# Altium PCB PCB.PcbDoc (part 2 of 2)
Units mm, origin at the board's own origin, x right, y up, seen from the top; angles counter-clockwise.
Board outline 106 x 80 mm, 4 copper layers (TOP, GND, SIG, BOTTOM), stack 1.586 mm thick; 94 components, 82 nets, 532 pads, 292 vias.
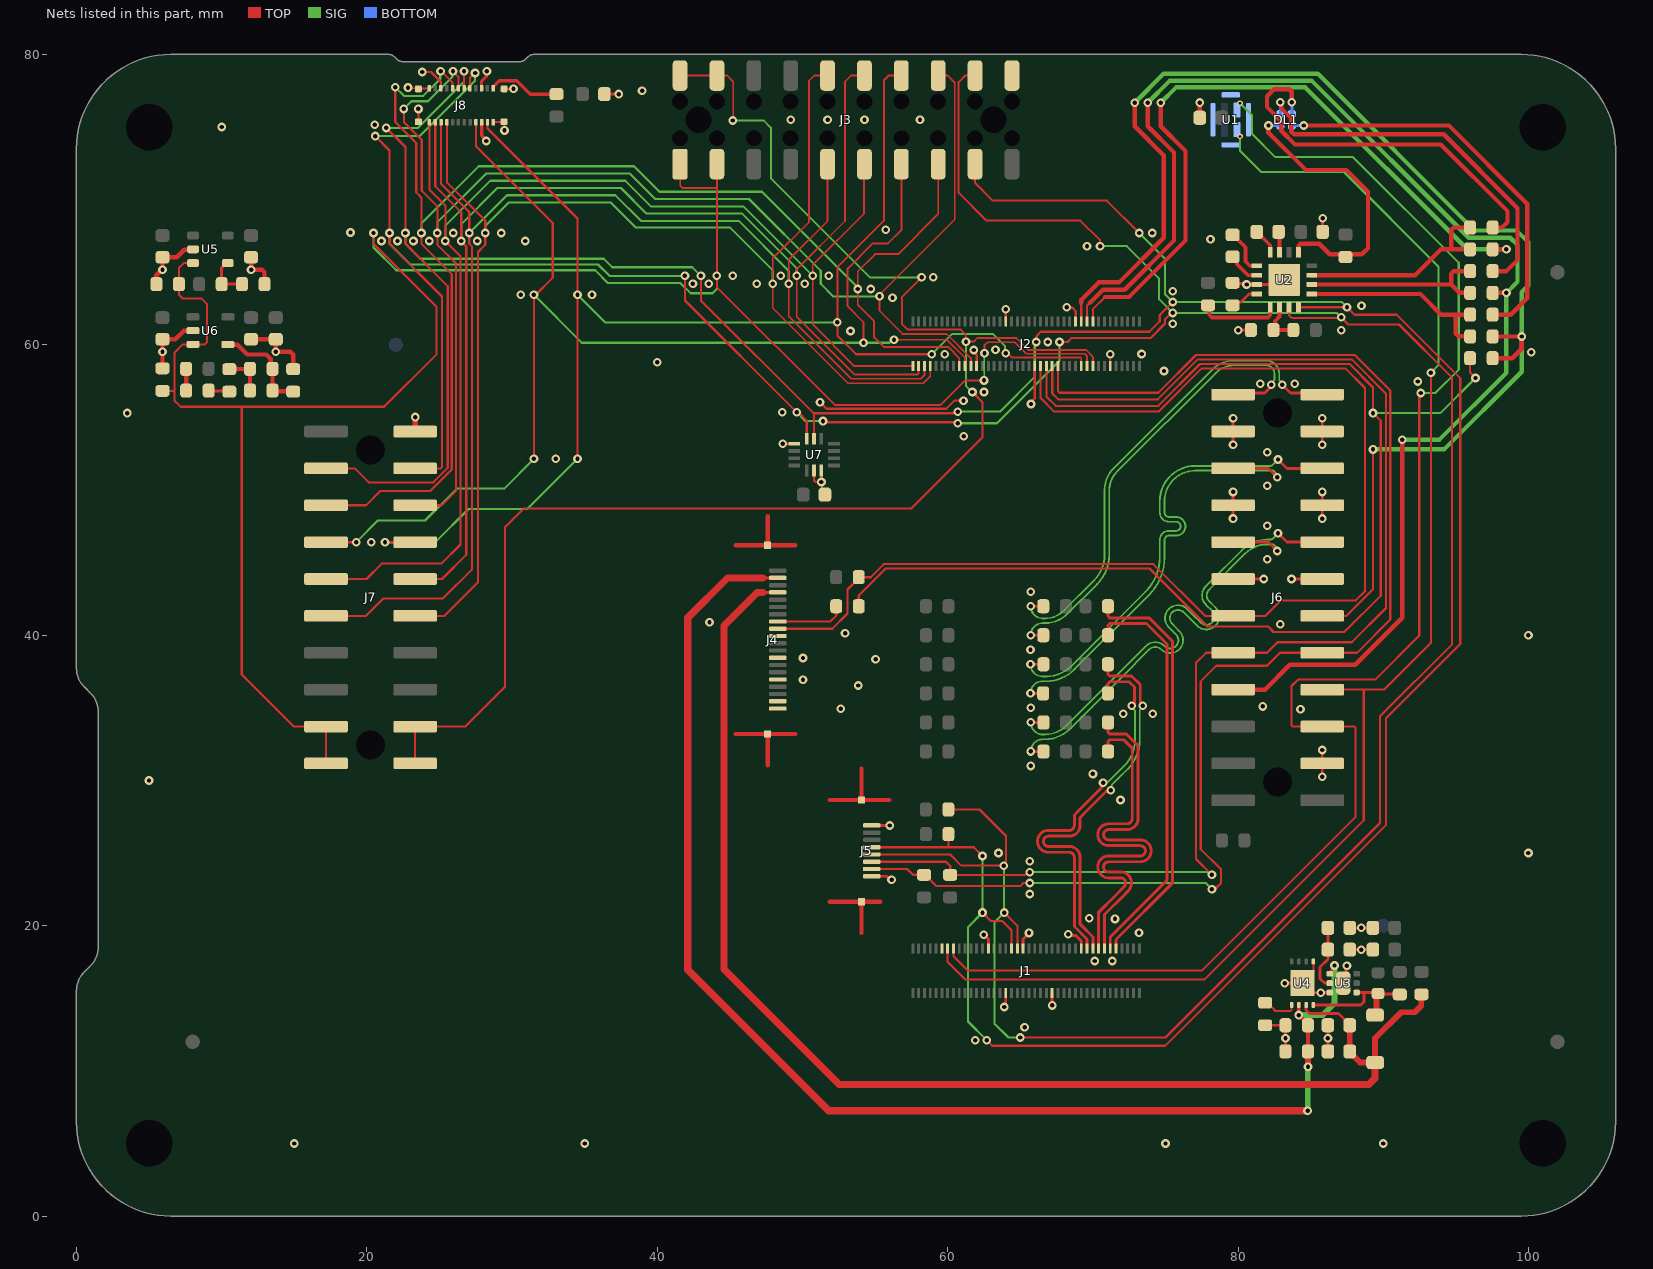
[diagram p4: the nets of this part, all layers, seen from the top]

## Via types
v1: diameter 0.6, hole 0.3, TOP to BOTTOM, tented both sides, 288 vias
v2: diameter 0.4, hole 0.2, TOP to BOTTOM, tented both sides, 4 vias

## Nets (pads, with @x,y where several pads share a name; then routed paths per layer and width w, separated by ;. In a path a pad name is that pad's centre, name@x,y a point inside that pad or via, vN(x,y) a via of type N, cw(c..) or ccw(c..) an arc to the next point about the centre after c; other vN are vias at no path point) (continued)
DOUT4: J2.8 J3.10 J7.12 J8.21 | length 94.1
  TOP w0.127: J3.10@51.731,78.55 50.819,78.55 50.45,78.182 50.45,68.45 47.956,65.956 v1(47.956,64.201) 47.956,62.538 53.136,57.358 58.335,57.358 58.801,57.824 J2.8@58.801,58.535
  TOP w0.15: J7.12@23.326,41.331 25.331,41.331 27.648,43.648 27.648,66.393 28.156,66.901 v1(28.156,67.701) 28.156,68.56 25.509,71.207 J8.21@25.509,75.334
  SIG w0.15: v1(28.156,67.701) 28.156,68.186 29.771,69.8 36.8,69.8 38.508,68.092 44.992,68.092 47.956,65.128 v1(47.956,64.201)
DOUT5: J2.6 J3.9 J7.11 J8.22 | length 92.6
  TOP w0.127: J3.9@51.731,72.45 51.731,68.531 49.056,65.856 v1(49.056,64.201) 49.056,61.973 53.366,57.663 58.163,57.663 58.401,57.901 J2.6@58.401,58.535
  TOP w0.15: J7.11@17.186,41.331 19.931,41.331 21.131,42.531 25.231,42.531 27.248,44.548 27.248,66.766 27.056,66.958 v1(27.056,67.701) 27.056,69.151 25.109,71.098 J8.22@25.109,75.334
  SIG w0.15: v1(27.056,67.701) 29.656,70.3 37.116,70.3 38.877,68.54 45.603,68.54 49.056,65.086 v1(49.056,64.201)
DOUT6: J2.4 J3.12 J7.10 J8.23 | length 92.7
  TOP w0.127: J3.12@54.271,78.55 53.35,78.55 52.931,78.131 52.931,68.531 49.606,65.206 49.606,61.938 53.58,57.963 57.927,57.963 58.001,58.038 J2.4@58.001,58.535
  TOP w0.15: J7.10@23.326,43.871 25.171,43.871 26.848,45.548 26.848,66.774 26.506,67.117 26.506,69.131 24.709,70.928 J8.23@24.709,75.334
  SIG w0.15: v1(26.506,67.151) 26.506,68.317 28.989,70.8 37.5,70.8 39.26,69.04 45.848,69.04 49.606,65.281 v1(49.606,64.751)
DOUT7: J2.2 J3.11 J7.9 J8.24 | length 91.2
  TOP w0.127: J3.11@54.271,72.45 54.24,72.419 54.24,69.04 50.706,65.506 v1(50.706,64.751) 50.706,61.407 53.578,58.535 J2.2@57.601,58.535
  TOP w0.15: J7.9@17.186,43.871 19.971,43.871 21.031,44.931 25.131,44.931 26.448,46.248 26.448,66.109 v1(25.406,67.151) 25.406,69.594 24.309,70.691 J8.24@24.309,75.334
  SIG w0.15: v1(25.406,67.151) 25.406,68.2 28.506,71.3 37.8,71.3 39.56,69.54 45.917,69.54 v1(50.706,64.751)
DSI_CK_2_N: J6.5 R32.1 | length 33.2
  TOP w0.2: v1(65.707,36) R32.1@66.58,36 ; J6.5@79.659,51.494 82.093,51.494 v1(82.707,50.88)
  SIG w0.127: v1(65.707,36) cw(c66.543,36) 66.543,36.837 ccw(c66.759,39.619) 68.731,37.645 73.872,42.785 ; 73.872,42.786 ccw(c71.307,45.35) 74.934,45.35 74.934,45.715 74.934,46.55 cw(c75.247,46.55) 75.247,46.863 75.736,46.863 ccw(c75.736,47.504) 75.736,48.144 75.247,48.144 cw(c75.247,48.458) 74.934,48.458 74.934,48.685 74.934,49.219 cw(c77.054,49.219) 77.054,51.339 82.385,51.339 cw(c82.385,51.212) 82.474,51.303 82.58,51.197 cw(c82.489,51.108) 82.616,51.108 82.616,50.971 v1(82.707,50.88)
DSI_CK_2_P: J6.6 R31.1 | length 33.2
  TOP w0.2: v1(65.707,38) R31.1@66.58,38 ; v1(82.751,52.108) 83.365,51.494 J6.6@85.799,51.494
  SIG w0.127: v1(65.707,38) ccw(c66.543,38) 66.54,37.164 ccw(c66.543,38) 66.543,37.164 cw(c66.543,36.836) 66.57,37.162 ccw(c66.759,39.619) 68.502,37.878 73.639,43.015 ccw(c71.302,45.352) 73.64,43.016 ccw(c71.302,45.352) 74.607,45.352 74.607,45.715 74.607,46.55 cw(c75.247,46.55) 75.247,47.19 75.736,47.19 ccw(c75.736,47.504) 75.736,47.817 75.247,47.817 cw(c75.247,48.458) 74.607,48.458 74.607,48.685 74.607,49.219 cw(c77.054,49.219) 77.054,51.666 82.257,51.666 ccw(c82.257,51.793) 82.347,51.703 ; 82.347,51.703 v1(82.751,52.108)
DSI_CK_3_N: J1.20 R4.1 | length 27.2
  TOP w0.2: J1.20@69.601,18.435 69.601,19.06 68.727,19.934 68.727,24.4 68.727,24.7 ccw(c68.373,24.7) 68.373,25.054 66.941,25.054 cw(c66.941,25.808) 66.941,26.562 68.373,26.562 ccw(c68.373,26.916) 68.727,26.916 68.727,27.624 69.029,27.926 70.63,29.527 70.63,29.774 v1(70.706,29.851) ; R4.1@71.039,36 71.039,36.683 71.156,36.8 72.5,36.8 72.864,36.437 72.864,35.326 v1(72.689,35.151)
  SIG w0.127: v1(70.706,29.851) 70.777,29.921 71.076,29.921 71.622,30.467 72.156,31.001 ccw(c70.36,32.797) 72.9,32.797 72.9,34.84 72.689,35.051 v1(72.689,35.151)
DSI_CK_3_P: J1.18 R3.1 | length 27.7
  TOP w0.2: J1.18@70.001,18.435 70.001,19.226 69.127,20.1 69.127,24.4 69.127,24.7 ccw(c68.373,24.7) 68.373,25.454 66.941,25.454 cw(c66.941,25.808) 66.941,26.162 68.373,26.162 ccw(c68.373,26.916) 69.127,26.916 69.127,27.458 69.595,27.926 70.913,29.244 71.16,29.244 v1(71.237,29.32) ; R3.1@71.039,38 71.039,37.317 71.156,37.2 72.089,37.2 72.666,37.2 73.264,36.602 73.264,35.326 v1(73.438,35.151)
  SIG w0.127: v1(71.237,29.32) 71.307,29.391 71.307,29.69 71.757,30.14 72.389,30.772 ccw(c70.365,32.795) 73.227,32.795 73.227,32.933 73.227,34.84 73.438,35.051 v1(73.438,35.151)
DSI_D0_2_N: J6.9 R34.1 | length 33.2
  TOP w0.2: v1(65.727,32) R34.1@66.6,32 ; J6.9@79.659,46.414 82.093,46.414 v1(82.707,45.8)
  SIG w0.127: v1(65.727,32) cw(c66.564,32) 66.564,32.837 66.71,32.837 ccw(c66.71,35.242) 68.41,33.541 71.942,37.073 73.9,39.031 cw(c74.299,38.633) 74.697,39.031 ccw(c75.327,39.661) 75.905,38.983 75.909,38.983 76.005,39.079 76.005,39.083 ccw(c75.327,39.661) 75.957,40.29 75.693,40.553 75.466,40.781 cw(c75.865,41.179) 75.466,41.578 cw(c75.865,41.179) 76.263,41.578 ; 76.264,41.577 77.187,40.654 ccw(c77.817,41.283) 78.447,40.654 ccw(c77.817,41.283) 78.447,41.913 78.415,41.945 78.013,42.347 cw(c78.411,42.745) 78.013,43.143 78.173,43.304 80.507,45.638 cw(c82.007,44.138) 82.007,46.259 82.385,46.259 cw(c82.385,46.132) 82.474,46.223 82.58,46.117 cw(c82.489,46.028) 82.616,46.028 82.616,45.891 v1(82.707,45.8)
DSI_D0_2_P: J6.10 R33.1 | length 33.2
  TOP w0.2: v1(65.727,34) R33.1@66.6,34 ; v1(82.751,47.028) 83.365,46.414 J6.10@85.799,46.414
  SIG w0.127: v1(65.727,34) ccw(c66.564,34) 66.564,33.163 66.707,33.163 ccw(c66.707,35.248) 68.181,33.774 71.711,37.304 73.669,39.262 cw(c74.299,38.633) 74.929,39.262 ; 74.929,39.262 ccw(c75.327,39.661) 75.725,39.262 ccw(c75.327,39.661) 75.725,40.059 75.235,40.549 cw(c75.865,41.179) 75.234,41.808 75.235,41.809 cw(c75.865,41.179) 76.442,41.857 76.446,41.857 76.923,41.381 77.419,40.885 ccw(c77.817,41.283) 78.215,40.885 ccw(c77.817,41.283) 78.215,41.682 77.782,42.115 cw(c78.411,42.745) 77.782,43.375 77.942,43.535 80.279,45.872 cw(c82.003,44.148) 82.003,46.586 82.257,46.586 ccw(c82.257,46.713) 82.347,46.623 ; 82.347,46.623 v1(82.751,47.028)
DSI_D0_3_N: J1.16 R6.1 | length 26.2
  TOP w0.2: J1.16@70.401,18.435 70.401,20.928 71.557,22.084 72.16,22.688 ccw(c71.91,22.938) 71.91,23.292 71.091,23.292 cw(c71.091,24.046) 70.337,24.046 cw(c71.091,24.046) 71.091,24.8 73.266,24.8 ccw(c73.266,25.154) 73.62,25.154 ccw(c73.266,25.154) 73.266,25.508 71.091,25.508 cw(c71.091,26.262) 70.337,26.262 cw(c71.091,26.262) 71.091,27.016 72.363,27.016 ccw(c72.363,27.37) 72.717,27.37 72.717,29.16 72.717,32.217 72.134,32.8 71.167,32.8 71.05,32.683 R6.1@71.05,32
DSI_D0_3_P: J1.14 R5.1 | length 26.8
  TOP w0.2: J1.14@70.801,18.435 70.801,20.763 72.122,22.084 72.443,22.405 ccw(c71.91,22.938) 71.91,23.692 71.091,23.692 cw(c71.091,24.046) 70.737,24.046 cw(c71.091,24.046) 71.091,24.4 73.266,24.4 ccw(c73.266,25.154) 74.02,25.154 ccw(c73.266,25.154) 73.266,25.908 71.091,25.908 cw(c71.091,26.262) 70.737,26.262 cw(c71.091,26.262) 71.091,26.616 72.363,26.616 ccw(c72.363,27.37) 73.117,27.37 73.117,29.16 73.117,32.383 72.3,33.2 71.167,33.2 71.05,33.317 R5.1@71.05,34
DSI_D1_2_N: J6.1 R36.1 | length 33
  TOP w0.2: v1(65.716,40) R36.1@66.589,40 ; J6.1@79.659,56.574 79.764,56.679 81.836,56.679 v1@82.352,57.194
  SIG w0.127: v1(65.716,40) cw(c66.553,40) 66.553,40.837 66.709,40.837 ccw(c66.709,43.003) 68.24,41.471 70.296,43.526 ccw(c68.272,45.55) 71.134,45.55 71.134,49.975 cw(c72.982,49.975) 71.674,51.281 ; 71.675,51.282 78.452,58.059 cw(c79.759,56.752) 78.453,58.06 cw(c79.759,56.752) 79.759,58.6 81.907,58.6 cw(c81.907,58) 82.507,58 82.507,57.901 82.507,57.562 82.296,57.35 v1(82.296,57.251)
DSI_D1_2_P: J6.2 R35.1 | length 33.5
  TOP w0.2: v1(65.716,42) R35.1@66.589,42 ; v1@83.09,57.206 83.617,56.679 85.694,56.679 J6.2@85.799,56.574
  SIG w0.127: v1(65.716,42) ccw(c66.553,42) 66.553,41.164 66.707,41.164 ccw(c66.707,43.007) 68.01,41.703 70.063,43.756 ccw(c68.267,45.552) 70.807,45.552 70.807,49.977 cw(c72.977,49.977) 71.442,51.511 ; 71.443,51.511 78.223,58.291 ; 78.223,58.292 cw(c79.757,56.757) 79.757,58.927 81.907,58.927 cw(c81.907,58) 82.834,58 82.834,57.765 82.834,57.562 83.046,57.35 v1(83.046,57.251)
DSI_D1_3_N: J1.12 R8.1 | length 28
  TOP w0.2: R8.1@71.039,40 71.039,40.683 71.156,40.8 73.7,40.8 75.1,39.4 75.1,23.119 71.201,19.221 J1.12@71.201,18.435
DSI_D1_3_P: J1.10 R7.1 | length 28.6
  TOP w0.2: R7.1@71.039,42 71.039,41.317 71.156,41.2 73.866,41.2 75.5,39.566 75.5,22.954 71.601,19.055 J1.10@71.601,18.435
GND: C1.1 C4.1 C5.1 C6.1 C7.1 C8.1 C9.1 C10.1 C11.1 C12.1 C13.1 C14.1 C15.1 C16.1 C17.1 J1.22 J1.31 J1.42 J1.47 J1.54 J2.24 J2.33 J2.44 J2.57 J2.70 J3.20 J4.1 J4.2 J4.5 J4.8 J4.11 J4.FIX1 J4.FIX2 J5.1 J5.8 J5.FIX1 J5.FIX2 J6.3 J6.4 J6.7 J6.8 J6.11 J6.12 J6.22 J7.2 J8.1 J8.3 J8.10 J8.13 J8.15 J8.M1 J8.M2 J8.M3 J8.M4 R10.2 R12.1 R28.1 R29.1 R30.1 R38.1 R39.1 R42.1 R47.1 U1.5 U2.11 U2.17 U3.3 U3.7 U4.1 U4.9 U5.2 U6.2 U7.1 U7.6 U7.7 | length 115.6
  TOP w0.127: v1(22.831,77.718) 22.875,77.674 23.507,77.674 J8.M4@23.551,77.63 23.571,77.65 24.281,77.65 J8.1@24.301,77.67 ; J8.M1@23.551,75.36 v1(23.551,76.251) ; J8.13@28.725,75.318 J8.13@28.709,75.334 28.722,75.347 29.438,75.347 J8.M2@29.451,75.36 29.463,75.348 29.463,74.783 v1(29.476,74.77) ; v1(71.196,59.356) 71.199,59.353 71.199,58.538 J2.70@71.201,58.535
  TOP w0.15: v1(23.821,78.789) 24.416,78.789 25.101,78.104 J8.3@25.101,77.67 ; J8.M3@29.451,77.63 v1(30.096,77.63) ; v1(48.65,53.194) U7.1@49.425,53.194 ; U7.6@50.8,51.344 50.8,50.657 50.906,50.551 v1(51.306,50.551) ; v1(51.206,56.051) 51.659,55.598 59.905,55.598 60.465,56.158 v1(61.088,56.158) ; U7.7@51.3,51.344 51.303,51.341 51.303,50.554 v1(51.306,50.551) ; C17.1@51.55,49.682 51.353,49.878 51.353,50.504 v1(51.306,50.551) ; v1(61.789,59.643) 61.789,59.515 62.001,59.302 J2.24@62.001,58.535 ; J2.33@64.001,61.615 v1(64.001,62.461) ; v1(65.744,55.927) 65.744,56.049 66.001,56.305 J2.44@66.001,58.535 ; v1(68.2,62.6) 68.248,62.552 68.595,62.552 68.825,62.322 68.825,62.096 68.807,62.078 68.807,61.621 J2.57@68.801,61.615 ; R30.1@81.865,13.14 R28.1@83.265,13.14 ; U4.9@84.44,16.04 85.19,16.79 U4.1@85.19,17.54
  TOP w0.2: J8.10@27.901,77.67 27.901,78.151 28.227,78.477 28.227,78.8 v1(28.268,78.841) ; C13.1@36.358,77.271 v1(37.348,77.271) ; J5.1@54.769,23.406 J5.1@54.771,23.404 55.785,23.404 56.03,23.159 v1(56.139,23.159) ; J5.8@54.771,26.904 56.003,26.904 v1(56.005,26.902) ; v1(62.48,19.378) 62.499,19.378 62.801,19.076 J1.54@62.801,18.435 ; v1(63.9,14.4) 63.9,14.508 64.001,14.609 J1.47@64.001,15.355 ; J1.42@65.201,18.435 65.201,19.085 65.6,19.484 v1(65.6,19.5) ; v1(67.201,14.506) J1.31@67.201,15.355 ; v1(68.307,19.4) 68.384,19.323 68.827,19.323 69.201,18.949 J1.22@69.201,18.435 ; R12.1@79.629,64.271 79.687,64.214 80.531,64.214 v1(80.589,64.156) U2.11@81.29,64.156 82.86,64.156 U2.17@83.185,64.481 ; J6.11@79.659,43.874 v1(81.781,43.874) ; v1(79.659,48.035) J6.7@79.659,48.954 v1(79.659,49.872) ; v1(79.659,53.115) J6.3@79.659,54.034 v1(79.659,54.952) ; v1(80.008,61.009) 80.016,61.017 80.794,61.017 R10.2@80.886,60.925 ; v1(83.217,16.04) U4.9@84.44,16.04 85.104,15.376 v1(85.696,15.376) 85.703,15.383 86.308,15.383 U3.3@86.315,15.39 ; R29.1@83.265,11.34 v1(83.265,12.24) R28.1@83.265,13.14 ; v1(83.678,43.874) J6.12@85.799,43.874 ; v1(85.799,30.255) J6.22@85.799,31.174 v1(85.799,32.092) ; v1(85.799,48.035) J6.8@85.799,48.954 v1(85.799,49.872) ; v1(85.799,53.115) J6.4@85.799,54.034 v1(85.799,54.952) ; v1(85.83,68.721) v1(85.83,68.721) C4.1@85.829,67.784 ; C8.1@86.19,11.34 v1(86.19,12.24) C7.1@86.19,13.14 ; U3.7@87.24,16.04 87.423,16.222 87.423,17.167 v1(87.499,17.243) ; C9.1@87.69,18.35 87.694,18.346 v1(88.495,18.346) 89.286,18.346 C6.1@89.29,18.35 ; C10.1@87.69,19.85 87.694,19.846 v1(88.495,19.846) 89.286,19.846 C5.1@89.29,19.85 ; C4.1@85.828,67.783 C4.1@85.829,67.784
  TOP w0.22: J8.15@27.909,75.334 27.909,74.415 28.231,74.093 v1(28.231,74.043)
  TOP w0.3: R38.1@5.507,64.181 5.5,64.188 5.5,64.8 5.881,65.181 v1(5.927,65.181) C11.1@5.927,66.031 ; R42.1@5.927,58.38 v1(5.927,59.531) C14.1@5.927,60.381 ; C14.1@6.061,60.381 6.8,60.381 7.382,60.963 8.008,60.963 U6.2@8.027,60.981 ; C11.1@6.226,66.031 6.914,66.031 7.43,66.547 7.992,66.547 U5.2@8.027,66.581 ; C16.1@12.027,60.381 C15.1@13.727,60.381 ; C12.1@12.026,66.031 v1(12.027,65.181) 12.776,65.181 12.952,65.005 R39.1@12.952,64.181 ; C15.1@13.727,60.381 v1(13.727,59.531) 14.727,59.531 14.927,59.331 R47.1@14.927,58.326 ; 45.404,33.2 J4.FIX2@47.601,33.2 ; 45.404,46.2 J4.FIX1@47.601,46.2 ; 47.601,31.035 J4.FIX2@47.601,33.2 ; 47.601,48.185 J4.FIX1@47.601,46.2 ; 49.501,33.2 J4.FIX2@47.601,33.2 ; 49.501,46.2 J4.FIX1@47.601,46.2 ; 51.874,21.654 J5.FIX2@54.071,21.654 ; 51.874,28.654 J5.FIX1@54.071,28.654 ; 54.071,19.489 J5.FIX2@54.071,21.654 ; 54.071,30.819 J5.FIX1@54.071,28.654 ; 55.349,21.654 J5.FIX2@54.071,21.654 ; 55.971,28.654 J5.FIX1@54.071,28.654 ; C1.1@77.358,75.644 77.36,75.646 77.36,76.684 v1(77.363,76.687)
  TOP w0.4: J7.2@23.326,54.031 v1(23.326,55.026)
  other v1: 15,5 35,5 75,5 90,5 61.9,12.1 65.3,13 70.136,17.561 71.336,17.561 73.176,19.509 71.526,20.464 69.755,20.513 65.659,22.184 65.659,24.434 63.5,25 100,25 71.906,28.651 5,30 70.006,30.451 65.727,31 72.1,34.6 74.127,34.6 84.3,34.9 52.638,34.938 65.727,35 81.7,35.1 53.838,36.538 50.038,36.938 55.038,38.338 50.038,38.438 65.707,39 100,40 52.938,40.138 82.906,40.751 43.6,40.9 65.716,43 82.007,45.242 20.296,46.413 82.007,47.542 82.007,50.3 33.006,52.151 82.007,52.6 61.1,53.7 3.5,55.3 48.606,55.351 62.506,56.751 81.537,57.324 83.916,57.324 92.385,57.481 74.9,58.2 40,58.8 59.806,59.351 73.358,59.371 100.2,59.5 63.299,59.662 66.9,60.2 53.306,60.951 87.1,61 75.5,61.45 88.5,62.7 56.206,63.251 30.606,63.451 35.506,63.451 75.5,63.7 54.706,63.851 42.456,64.201 43.556,64.201 46.856,64.201 50.156,64.201 59.006,64.651 45.206,64.751 48.506,64.751 51.806,64.751 69.6,66.8 21.006,67.151 22.106,67.151 23.206,67.151 24.306,67.151 27.606,67.151 30.906,67.151 78.105,67.275 25.956,67.701 29.256,67.701 74.1,67.7 18.871,67.737 55.735,67.931 10,75 20.545,75.15 49.2,75.5 51.731,75.5 54.271,75.5 58.1,75.5 38.956,77.505
HREF: J2.22 J3.16 J7.6 J8.6 | length 101.1
  TOP w0.127: v1(25.931,78.85) 26.301,78.481 J8.6@26.301,77.67 ; J3.16@59.351,78.55 60.007,78.55 60.49,78.068 60.49,68.635 55.306,63.451 55.306,62.344 56.901,60.749 59.942,60.749 61.601,59.09 J2.22@61.601,58.535
  TOP w0.15: v1(22.551,76.251) 22.551,75.348 23.785,74.114 23.785,70.615 24.856,69.544 v1(24.856,67.701) 24.856,66.901 26.148,65.609 26.148,49.948 25.151,48.951 J7.6@23.326,48.951
  SIG w0.15: v1(22.551,76.251) 23.076,76.776 24.206,76.776 25.885,78.454 25.885,78.804 v1(25.931,78.85) ; v1(24.856,67.701) 24.856,68.438 28.218,71.8 38.1,71.8 39.86,70.04 46.317,70.04 51.256,65.101 51.256,64.201 52.131,63.326 55.281,63.326 v1(55.306,63.351)
LEDA_4: C7.2 C8.2 D1.C J4.17 R25.2 U4.7 | length 91.9
  TOP w0.2: 47.27,42.944 47.276,42.95 J4.17@48.301,42.95 ; U4.7@84.69,14.54 84.69,14.19 84.928,13.952 86.928,13.952 C7.2@87.69,13.19
  TOP w0.4: C8.2@87.69,11.34 87.69,11.29 88.41,10.57 D1.C@89.44,10.57 89.44,12.24 91.24,14.04 92.171,14.04 92.62,14.489 92.62,15.245 R25.2@92.64,15.265 ; C8.2@87.69,11.44 C7.2@87.69,13.19
  TOP w0.5: 47.27,42.944 46.881,42.944 44.6,40.664 44.6,16.995 52.539,9.056 89.008,9.056 89.44,9.488 D1.C@89.44,10.57
LEDK_4: J4.19 R28.2 R29.2 U3.1 U4.6 | length 92
  TOP w0.2: 47.265,43.94 47.276,43.95 J4.19@48.301,43.95 ; U3.1@86.315,16.69 86.34,16.69 86.44,16.79 86.44,16.941 86.646,17.147 v1(86.646,17.255)
  TOP w0.25: U4.6@84.19,14.54 v1(84.19,13.84) 84.815,13.215 R28.2@84.815,13.14 R29.2@84.815,11.34
  TOP w0.4: v1(84.815,10.275) R29.2@84.815,11.34
  TOP w0.5: 47.265,43.94 44.84,43.94 42.1,41.2 42.1,16.955 51.805,7.25 v1(84.79,7.25)
  SIG w0.4: v1(84.19,13.84) 85.83,13.84 86.646,14.656 v1(86.646,17.255) ; v1(84.79,7.25) 84.803,7.262 84.803,10.262 v1(84.815,10.275)
nBLUE_1: J2.63 R50.2 | length 49.2
  TOP w0.15: J2.63@70.001,61.615 70.001,62.451 70.85,63.3
  TOP w0.3: 70.85,63.3 72.5,63.3 76.385,67.185 76.385,73.351 74.685,75.051 v1(74.685,76.681) ; R50.2@97.535,66.581 v1(98.485,66.581)
  SIG w0.3: v1(74.685,76.681) 75.735,77.731 84.635,77.731 95.785,66.581 v1(98.485,66.581)
NetC2_1: C2.1 U2.8 | length 1.8
  TOP w0.25: C2.1@81.292,67.778 82.21,66.86 U2.8@82.21,66.376
NetC2_2: C2.2 U2.7 | length 1.4
  TOP w0.25: C2.2@82.792,67.783 82.86,67.715 U2.7@82.86,66.376
NetC3_1: C3.1 U2.9 | length 3.1
  TOP w0.25: C3.1@79.629,67.571 79.679,67.571 80.518,66.732 80.518,65.751 80.813,65.456 U2.9@81.29,65.456
NetC3_2: C3.2 U2.10 | length 2.3
  TOP w0.25: C3.2@79.629,66.071 79.925,65.775 79.925,65.546 80.665,64.806 U2.10@81.29,64.806
NetC9_2: C9.2 C10.2 U3.2 | length 4.5
  TOP w0.2: C10.2@86.19,19.85 86.19,17.69 85.653,17.153 85.653,16.337 85.95,16.04 U3.2@86.315,16.04
NetD1_A: D1.A L1.2 R26.2 U3.4 U4.8 | length 8.8
  TOP w0.2: U4.8@85.19,14.54 88.453,14.54 88.673,14.76 88.673,15.397 88.663,15.407 ; U3.4@88.165,15.39 88.182,15.407 88.663,15.407 ; R26.2@91.14,15.265 91.108,15.297 89.673,15.297 L1.2@89.64,15.33 89.563,15.407 88.663,15.407
  TOP w0.4: D1.A@89.44,13.84 89.54,13.94 89.54,15.23 L1.2@89.64,15.33
NetDL1_1: DL1.1 R51.1 U2.5 | length 19.5
  TOP w0.3: v1(82.095,75.105) 82.081,75.091 82.081,74.63 84.672,72.038 87.462,72.038 88.953,70.547 88.953,66.658 88.528,66.233 87.403,66.233 86.323,66.233 85.594,66.962 84.306,66.962 84.16,66.815 U2.5@84.16,66.376
  BOTTOM w0.2: v1(82.095,75.105) DL1.1@82.917,75.105
NetDL1_2: DL1.2 R13.2 | length 27.8
  TOP w0.3: v1(84.528,75.105) 94.528,75.105 99.907,69.726 99.907,63.203 98.785,62.081 R13.2@97.535,62.081
  BOTTOM w0.2: DL1.2@83.707,75.105 v1(84.528,75.105)
NetDL1_3: DL1.3 R15.2 | length 26.1
  TOP w0.3: v1(83.707,76.717) 83.707,77.424 83.531,77.6 82.476,77.6 82,77.124 82,76.38 82.973,75.407 82.973,74.751 83.925,73.8 93.966,73.8 98.554,69.212 98.554,68.45 98.185,68.081 R15.2@97.535,68.081
  BOTTOM w0.2: DL1.3@83.707,75.895 v1(83.707,76.717)
NetDL1_4: DL1.4 R14.2 | length 26.5
  TOP w0.3: v1(82.917,76.717) 82.968,76.665 82.968,76.307 83.677,75.598 83.677,74.684 83.856,74.505 94.161,74.505 99.25,69.416 99.25,65.846 98.485,65.081 R14.2@97.535,65.081
  BOTTOM w0.2: DL1.4@82.917,75.895 v1(82.917,76.717)
NetJ1_70: J1.70
NetJ2_48: J2.48 R52.1 R53.2 | length 91.1
  TOP w0.15: R52.1@53.875,42 53.875,42.736 55.739,44.6 73.9,44.6 77.9,40.6 82.075,40.6 82.449,40.226 87.326,40.226 89.825,42.725 89.825,54.775 v1(89.3,55.3) 89.3,57.066 87.685,58.681 77.385,58.681 74.504,55.8 67.449,55.8 66.801,56.448 J2.48@66.801,58.535 ; R53.2@95.985,59.081 95.985,58.09 v1(96.353,57.722)
  SIG w0.15: v1(89.3,55.3) 93.931,55.3 v1(96.353,57.722)
NetJ4_13: J4.13 R52.2 | length 4.8
  TOP w0.15: J4.13@48.301,40.95 51.925,40.95 52.325,41.351 R52.2@52.325,42
NetJ8_12: J8.12 R40.2 | length 5
  TOP w0.23: J8.12@28.701,77.67 28.706,77.675 28.706,77.78 29.121,78.195 30.33,78.195 31.254,77.271 R40.2@33.058,77.271
NetR9_1: R9.1 R10.1 U2.14 | length 3.1
  TOP w0.25: U2.14@82.86,62.586 82.86,61.947 82.548,61.635 82.548,61.137 R10.1@82.436,61.025 R9.1@83.807,61.025
NetR11_1: R11.1 U2.13 | length 5.6
  TOP w0.25: R11.1@77.929,62.721 78.018,62.632 78.018,62.082 78.214,61.886 82.064,61.886 82.21,62.032 U2.13@82.21,62.586
NetR12_2: R12.2 U2.12 | length 2
  TOP w0.2: R12.2@79.629,62.721 79.852,62.944 80.202,62.944 80.759,63.501 81.285,63.501 U2.12@81.29,63.506
NetR13_1: R13.1 R48.1 U2.1 | length 13.9
  TOP w0.3: U2.1@85.08,63.506 92.56,63.506 93.985,62.081 94.985,62.081 ; R48.1@95.985,60.581 95.185,60.581 94.985,60.781 94.985,62.081 ; R13.1@95.985,62.081 94.985,62.081
NetR14_1: R14.1 R49.1 U2.2 | length 13.3
  TOP w0.3: U2.2@85.08,64.156 94.684,64.156 ; R49.1@95.985,63.581 95.259,63.581 94.684,64.156 ; R14.1@95.985,65.081 94.86,65.081 94.684,64.905 94.684,64.156
NetR15_1: R15.1 R50.1 U2.3 | length 14.3
  TOP w0.3: U2.3@85.08,64.806 92.21,64.806 93.985,66.581 94.679,66.581 ; R50.1@95.985,66.581 94.679,66.581 ; R15.1@95.985,68.081 94.855,68.081 94.679,67.905 94.679,66.581
NetR30_2: R30.2 U4.5 | length 2.4
  TOP w0.15: R30.2@81.865,14.69 82.013,14.69 82.333,14.37 82.335,14.37 82.578,14.127 83.602,14.127 83.69,14.215 U4.5@83.69,14.54
NetR37_1: R37.1 R39.2 U5.4 | length 3.1
  TOP w0.2: U5.4@10.426,65.631 10.322,65.631 10.002,65.311 R37.1@10.002,64.181 R39.2@11.402,64.181
NetR41_1: R41.1 R43.2 | length 1.5
  TOP w0.3: R43.2@7.552,56.851 R41.1@7.552,58.351
NetR43_1: R43.1 R44.2 | length 1.5
  TOP w0.2: R43.1@9.102,56.851 9.139,56.814 10.489,56.814 R44.2@10.527,56.776
NetR44_1: R44.1 R45.1 R46.1 | length 2.9
  TOP w0.3: R44.1@10.527,58.326 10.539,58.339 11.939,58.339 R45.1@11.952,58.351 R46.1@11.952,56.851
NetR45_2: R45.2 R46.2 R47.2 U6.4 | length 7.1
  TOP w0.3: U6.4@10.427,60.031 10.441,60.017 11.075,60.017 11.761,59.331 13.078,59.331 13.375,59.034 13.375,58.477 R45.2@13.502,58.351 ; R45.2@13.502,58.458 R46.2@13.502,56.851 13.539,56.814 R47.2@14.889,56.814
nGREEN_1: J2.61 J6.17 R49.2 | length 95.1
  TOP w0.15: J2.61@69.601,61.615 69.601,62.697 69.785,62.881
  TOP w0.3: 69.785,62.881 70.704,63.8 72.2,63.8 75.585,67.185 75.585,73.251 73.785,75.051 v1(73.785,76.681) ; J6.17@79.659,36.254 81.858,36.254 83.568,37.964 88.068,37.964 91.313,41.209 v1(91.313,53.474) ; R49.2@97.535,63.581 v1(98.485,63.581)
  SIG w0.3: v1(73.785,76.681) 75.285,78.181 85.085,78.181 95.885,67.381 98.756,67.381 99.25,66.887 99.25,64.346 v1(98.485,63.581) 98.485,58.081 93.878,53.474 v1(91.313,53.474)
nRED_1: J2.59 J6.14 R48.2 R53.1 | length 92.4
  TOP w0.15: J2.59@69.201,61.615 69.201,62.897 ; J6.14@85.799,41.334 87.465,41.334 89.3,43.169 v1(89.3,52.8)
  TOP w0.3: 69.201,62.897 69.201,63.097 70.404,64.3 71.804,64.3 74.885,67.381 74.885,73.051 72.885,75.051 v1(72.885,76.681) ; R53.1@97.535,59.081 98.885,59.081 99.535,59.731 v1(99.535,60.574) 99.532,60.578 97.538,60.578 R48.2@97.535,60.581
  SIG w0.3: v1(72.885,76.681) 74.885,78.681 85.485,78.681 96.285,67.881 99.185,67.881 99.985,67.081 99.985,64.081 99.535,63.631 v1(99.535,60.574) 99.535,58.14 94.195,52.8 v1(89.3,52.8)
PA1: J2.62 J3.1 J3.3 J7.17 J7.19 R38.2 R42.2 U5.3 U6.3 | length 145.2
  TOP w0.127: J3.1@41.571,72.45 41.584,72.437 41.584,70.951 41.729,70.806 44.111,70.806 ; J3.3@44.111,72.45 44.111,70.806 ; v1(62.506,57.551) 61.207,57.551 59.519,55.863 52.23,55.863 44.111,63.983 44.111,70.806 ; v1(62.535,59.421) 62.535,59.962 62.752,60.178 64.623,60.178 65.408,59.393 69.435,59.393 69.601,59.227 J2.62@69.601,58.535
  TOP w0.15: R42.2@5.927,56.83 6.74,56.83 ; 6.755,59.459 6.755,56.161 7.176,55.739 11.387,55.739 ; 6.765,59.47 7.327,60.031 U6.3@8.027,60.031 8.831,60.031 9,60.2 9,62.8 8.6,63.2 7.3,63.2 7.057,63.443 R38.2@7.057,64.181 7.057,65.306 7.382,65.631 U5.3@8.027,65.631 ; J7.19@17.186,31.171 J7.17@17.186,33.711 14.969,33.711 11.387,37.293 11.387,55.739 ; v1(20.456,67.701) 20.456,66.958 24.806,62.608 24.806,59.362 21.184,55.739 11.387,55.739
  SIG w0.127: v1(62.506,57.551) 62.521,57.565 62.521,59.407 v1(62.535,59.421)
  SIG w0.15: v1(20.456,67.701) 20.456,66.701 22.024,65.133 35.724,65.133 36.606,64.251 41.606,64.251 42.306,63.551 43.806,63.551 44.106,63.851 v1(44.106,64.751)
PA6: J2.20 J3.13 J7.7 J8.16 | length 89.8
  TOP w0.127: v1(54.206,60.151) 54.206,61.563 53.106,62.663 53.106,65.251 54.846,66.991 55.891,66.991 56.831,67.931 56.831,72.43 J3.13@56.811,72.45 ; v1(56.306,60.351) 59.945,60.351 61.201,59.095 J2.20@61.201,58.535
  TOP w0.15: J7.7@17.186,46.411 v1(19.262,46.411) ; J8.16@27.509,75.334 27.509,73.691 32.806,68.394 32.806,64.629 31.506,63.329 v1(31.506,52.151)
  SIG w0.15: v1(19.262,46.411) 20.751,47.9 24,47.9 26.2,50.1 29.456,50.1 v1(31.506,52.151) ; v1(31.506,63.451) 34.806,60.151 44.345,60.151 55.993,60.151 56.193,60.351 v1(56.306,60.351)
PB6: J1.46 J3.17 J5.5 J7.3 J8.7 R1.1 U2.16 U7.13 | length 247.3
  TOP w0.15: J7.3@17.186,51.491 19.171,51.491 20.131,50.531 24.575,50.531 25.571,51.527 25.571,64.043 22.656,66.958 v1(22.656,67.701) 22.656,73.628 v1(21.344,74.941) ; v1(26.686,78.85) 26.693,78.843 26.693,77.678 J8.7@26.701,77.67 ; v1(43.006,64.751) 43.006,63.061 50.772,55.294 ; U7.13@50.8,53.544 50.8,55.267 50.772,55.294 ; J5.5@54.771,25.404 60.078,25.404 ; R1.1@60.05,26.3 60.05,25.432 60.078,25.404 ; v1(60.7,55.4) 60.614,55.314 60.407,55.314 60.387,55.294 50.772,55.294 ; J3.17@61.891,72.45 61.891,71.15 63.107,69.934 70.966,69.934 v1(73.2,67.7) ; v1@62.334,24.734 v1(62.4,24.8) 61.796,25.404 60.078,25.404 ; v1(62.4,20.9) 62.991,20.309 63.781,20.309 64.401,19.689 J1.46@64.401,18.435 ; v1(62.7,12.1) 63.069,11.731 74.979,11.731 90.2,26.951 90.2,34.3 95.3,39.4 95.3,57.706 90.931,62.075 88.025,62.075 v1(87.5,62.6) 87.486,62.586 U2.16@84.16,62.586 ; v1(66.1,60.2) 66.131,60.231 66.131,60.612 66.419,60.9 73.885,60.9 74.613,61.628 74.613,62.055 75.5,62.942 v1(75.5,62.95)
  SIG w0.15: v1(21.344,74.941) 23.496,74.941 26.686,78.13 v1(26.686,78.85) ; v1(22.656,67.701) 22.656,66.958 23.682,65.933 36.324,65.933 36.906,65.351 42.406,65.351 v1(43.006,64.751) ; v1(60.7,55.4) 63.6,55.4 66,57.8 66,59.887 66.014,59.901 66.014,60.114 v1(66.1,60.2) ; v1(62.4,24.8) 62.4,21.068 62.484,20.984 v1(62.4,20.9) 61.4,19.9 61.4,13.4 v1(62.7,12.1) ; v1(73.2,67.7) 74.975,65.925 74.975,63.483 74.988,63.47 74.988,63.462 v1(75.5,62.95) 87.15,62.95 v1(87.5,62.6)
PC1: J1.68 J6.18 U1.4 | length 96.5
  TOP w0.15: J1.68@60.001,18.435 60.001,17.499 61.2,16.3 77.7,16.3 88.656,27.256 88.656,36.254 ; J6.18@85.799,36.254 88.656,36.254 ; v1(93.285,58.081) 93.285,39.485 90.054,36.254 88.656,36.254
  SIG w0.15: v2(80.132,74.361) 80.132,73.571 80.132,73.368 81.6,71.9 87.3,71.9 93.8,65.4 93.8,58.596 v1(93.285,58.081)
PC6: J2.46 J4.12 J6.13 R24.1 | length 86.2
  TOP w0.15: J4.12@48.301,40.45 52.05,40.45 53.1,41.501 53.1,43.15 53.875,43.925 R24.1@53.875,44 54.701,44 55.601,44.9 74.157,44.9 77.723,41.334 J6.13@79.659,41.334 81.889,41.334 82.956,42.4 88.107,42.4 88.743,43.036 88.743,57.024 87.387,58.381 77.509,58.381 74.528,55.4 67.349,55.4 66.401,56.348 J2.46@66.401,58.535
PD3: J1.66 J6.20 U1.3 | length 104.3
  TOP w0.15: J1.66@60.401,18.435 60.401,17.899 61.4,16.9 77.5,16.9 88.1,27.5 88.1,33.626 88.012,33.714 J6.20@85.799,33.714 83.774,33.714 83.686,33.802 83.686,36.505 84.125,36.943 89.443,36.943 92.485,39.985 92.485,56.368 92.499,56.382 92.499,56.595 v1(92.585,56.681)
  SIG w0.15: v2(80.132,76.639) 80.958,75.813 80.958,74.542 82.571,72.929 87.922,72.929 95.2,65.651 95.2,58.296 93.585,56.681 v1(92.585,56.681)
PD4: J2.64 J3.2 J3.4 J7.18 J7.20 | length 108.3
  TOP w0.127: J3.2@41.571,78.55 J3.4@44.111,78.55 44.812,78.55 45.231,78.131 45.231,75.475 v1(45.206,75.451) ; v1(58.206,64.651) 56.848,63.292 56.848,61.457 57.254,61.051 60.911,61.051 61.251,60.711 61.251,60.23 v1(61.261,60.22) 61.791,60.22 62.042,60.471 64.731,60.471 65.555,59.647 69.54,59.647 70.001,59.186 J2.64@70.001,58.535
  TOP w0.15: J7.20@23.326,31.171 23.326,33.631 23.406,33.711 26.767,33.711 29.524,36.469 29.524,47.457 30.8,48.733 57.489,48.733 62.4,53.644 62.4,56.057 v1(61.706,56.751)
  SIG w0.127: v1(45.206,75.451) 47.344,75.451 47.831,74.964 47.831,71.469 54.649,64.651 v1(58.206,64.651) ; v1(61.261,60.22) 61.261,57.196 v1(61.706,56.751)
PH12: J1.44 J3.18 J5.4 J7.4 J8.8 R2.1 U2.15 U7.14 | length 253.4
  TOP w0.15: v1(20.568,74.378) 21.556,73.39 v1(21.556,67.701) 21.581,67.676 21.581,66.933 25.18,63.334 25.18,51.579 25.092,51.491 J7.4@23.326,51.491 ; J8.8@27.101,77.67 27.101,78.404 ; 27.131,78.432 27.419,78.72 v1(27.455,78.72) ; v1(41.906,64.751) 41.906,63.051 v1(49.606,55.351) 49.728,55.351 50.3,54.779 U7.14@50.3,53.544 ; v1(51.414,54.75) 51.489,54.675 60.503,54.675 60.578,54.6 v1(60.7,54.6) ; J5.4@54.771,24.904 60.171,24.904 60.941,24.134 v1(63.859,24.134) 63.859,24.256 64.025,24.421 64.025,26.173 62.198,28 R2.1@60.05,28 ; J3.18@61.891,78.55 61.221,78.55 60.756,78.085 60.756,70.469 62.67,68.555 69.14,68.555 70.5,67.195 v1(70.5,66.8) ; v1(63.9,20.9) 64.801,19.999 J1.44@64.801,18.435 ; v1(65,12.3) 75,12.3 89.775,27.075 89.775,34.415 94.746,39.386 94.746,57.74 91.087,61.4 87.6,61.4 v1(87.1,61.9) 87.055,61.855 83.69,61.855 83.51,62.035 U2.15@83.51,62.586 ; v1(67.7,60.2) 68.251,60.2 68.513,60.461 73.97,60.461 74.975,61.466 74.975,61.768 75.407,62.2 v1(75.5,62.2)
  SIG w0.15: v1(20.568,74.378) 23.634,74.378 27.45,78.195 27.45,78.715 v1(27.455,78.72) ; v1(21.556,67.701) 21.556,66.958 22.982,65.533 35.924,65.533 36.706,64.751 v1(41.906,64.751) ; v1(49.606,55.351) 50.207,54.75 v1(51.414,54.75) ; v1(60.7,54.6) 63.4,54.6 67.7,58.9 v1(67.7,60.2) ; v1(63.859,24.134) 63.88,24.113 63.88,20.92 v1(63.9,20.9) 63.232,20.232 63.232,13.253 64.185,12.3 v1(65,12.3) ; v1(70.5,66.8) 72.331,66.8 74.567,64.563 74.567,63.133 v1(75.5,62.2) 86.8,62.2 v1(87.1,61.9)
PI1: J2.50 J5.3 J6.15 R21.1 | length 95.9
  TOP w0.15: J5.3@54.771,24.404 59.882,24.404 60.175,24.111 R21.1@60.175,23.496 65.35,23.496 65.537,23.684 v1(65.659,23.684) ; J2.50@67.201,58.535 67.201,56.656 67.614,56.244 74.468,56.244 77.224,59 87.824,59 90.189,56.635 90.189,41.882 87.827,39.52 82.72,39.52 81.994,38.794 J6.15@79.659,38.794 77.801,38.794 77.107,38.1 77.107,24.593 v1(78.2,23.5)
  SIG w0.15: v1(65.659,23.684) 77.894,23.684 78.078,23.5 v1(78.2,23.5)
PI2: J2.52 J5.2 J6.16 R18.1 | length 96.8
  TOP w0.15: J5.2@54.771,23.904 57.207,23.904 57.611,23.5 R18.1@58.375,23.5 58.45,23.5 59.229,22.721 64.996,22.721 65.209,22.934 v1(65.659,22.934) ; J2.52@67.601,58.535 67.601,56.799 67.7,56.7 74.5,56.7 77.1,59.3 88.045,59.3 90.489,56.856 90.489,41.082 88.201,38.794 J6.16@85.799,38.794 82.894,38.794 82,37.9 78.507,37.9 77.43,36.823 77.43,25.27 78.834,23.866 78.834,22.934 78.486,22.586 78.286,22.586 v1(78.2,22.5)
  SIG w0.15: v1(65.659,22.934) 77.766,22.934 v1(78.2,22.5)
PI5: J2.18 J3.15 J7.5 J8.5 | length 102.1
  TOP w0.127: v1(25.077,78.838) 25.125,78.838 25.901,78.061 J8.5@25.901,77.67 ; J3.15@59.351,72.45 59.351,69.018 56.584,66.251 55.006,66.251 53.806,65.051 v1(53.806,63.851) 53.806,62.751 54.939,61.618 54.939,60.518 55.597,59.86 56.509,59.86 56.513,59.864 60.019,59.864 60.023,59.86 60.033,59.86 60.801,59.092 J2.18@60.801,58.535
  TOP w0.15: J7.5@17.186,48.951 19.951,48.951 20.931,49.931 24.367,49.931 25.848,51.413 25.848,64.866 23.756,66.958 v1(23.756,67.701) 23.756,70.144 23.396,70.504 23.396,73.906 21.953,75.349 21.953,76.445 21.951,76.447 v1(21.951,77.751)
  SIG w0.15: v1(21.951,77.751) 22.553,77.149 23.89,77.149 25.054,78.313 25.054,78.814 v1(25.077,78.838) ; v1(23.756,67.701) 23.756,68.356 27.7,72.3 38.4,72.3 40.16,70.54 47.217,70.54 53.806,63.951 v1(53.806,63.851)
PJ9: J2.60 J3.14 J7.8 J8.14 | length 101.8
  TOP w0.127: v1(64.012,59.417) 64.14,59.417 64.417,59.139 69.127,59.139 69.201,59.064 J2.60@69.201,58.535
  TOP w0.15: v1(21.251,46.411) J7.8@23.326,46.411 ; J8.14@28.309,75.334 28.309,74.895 34.506,68.698 v1(34.506,63.451) v1(34.506,52.151) ; J3.14@56.811,78.55 55.95,78.55 55.606,78.206 55.606,68.551 52.406,65.351 v1(52.406,61.551) 52.406,60.651 53.706,59.351 v1(58.906,59.351)
  SIG w0.15: v1(21.251,46.411) 24.711,46.411 27,48.7 31.056,48.7 v1(34.506,52.151) ; v1(34.506,63.451) 36.406,61.551 v1(52.406,61.551) ; v1(58.906,59.351) 60.312,60.756 61.514,60.756 63.106,60.756 63.959,59.903 63.959,59.47 v1(64.012,59.417)
pads on no net: Fiducial_1.1 Fiducial_2.1 Fiducial_3.1 Fiducial_4.1 Fiducial_5.1 J1.1 J1.2 J1.3 J1.4 J1.5 J1.6 J1.7 J1.8 J1.9 J1.11 J1.13 J1.15 J1.17 J1.19 J1.23 J1.24 J1.25 J1.26 J1.27 J1.28 J1.29 J1.30 J1.33 J1.34 J1.35 J1.36 J1.37 J1.38 J1.39 J1.40 J1.43 J1.45 J1.49 J1.50 J1.51 J1.52 J1.53 J1.55 J1.56 J1.57 J1.58 J1.59 J1.60 J1.61 J1.62 J1.63 J1.64 J1.65 J1.67 J1.69 J1.71 J1.72 J1.73 J1.74 J1.75 J1.76 J1.77 J1.78 J1.79 J1.80 J2.1 J2.3 J2.5 J2.7 J2.9 J2.11 J2.13 J2.15 J2.17 J2.19 J2.21 J2.25 J2.26 J2.27 J2.28 J2.29 J2.30 J2.31 J2.32 J2.35 J2.36 J2.37 J2.38 J2.39 J2.40 J2.41 J2.42 J2.45 J2.47 J2.49 J2.51 J2.53 J2.54 J2.55 J2.56 J2.58 J2.65 J2.67 J2.68 J2.71 J2.72 J2.73 J2.74 J2.75 J2.76 J2.77 J2.78 J2.79 J2.80 J3.0 J4.16 J4.18 J4.20 J5.7 J6.24 J6.ALIGN1 J6.ALIGN2 J7.ALIGN1 J7.ALIGN2 J8.4 J8.9 U2.4 U4.4 U7.2 U7.3 U7.4 U7.9 U7.10 U7.11

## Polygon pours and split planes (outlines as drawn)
GND on SIG "GND_L03_P007" (solid, remove dead copper, pour order 7): 0,6.5 0,15.521 cw(c1.811,15.521) 0.53,16.802 0.531,16.802 0.971,17.241 ccw(c-0.31,18.521) 1.501,18.521 1.501,34.727 ccw(c-0.31,34.727) 0.971,36.008 0.531,36.447 0.53,36.447 cw(c1.811,37.727) 0,37.727 0,73.5 cw(c6.5,73.5) 6.5,80 21.501,80 cw(c21.501,79.397) 21.928,79.824 22.074,79.677 ccw(c22.501,80.104) 22.501,79.5 30.501,79.5 ccw(c30.501,80.104) 30.928,79.677 31.074,79.824 cw(c31.501,79.397) 31.501,80 99.499,80 cw(c99.499,80) 99.5,80 cw(c99.5,73.5) 106,73.5 106,6.5 cw(c99.5,6.5) 99.5,0 6.5,0 cw(c6.5,6.5)
+3V3 on SIG "+3V3_L03_P002" (solid, remove dead copper, pour order 2): 49.554,51.32 53.2,45.4 53.2,42.206 47.1,42.206 47.1,26.447 56.9,26.447 56.9,22.4 56.9,13.011 60.855,9.056 68.528,9.056 81.473,22.002 81.473,24.662 78.571,27.564 78.571,28.417 80.215,28.417 80.583,28.417 81.585,28.417 85.75,24.251 85.75,19.314 69.287,2.851 51.888,2.851 40.737,14.002 40.737,50.781 41.276,51.32
+3V3 on SIG "+3V3_L03_P005" (solid, remove dead copper, pour order 5): 16.9,70 16.9,66.1 24.793,58.207 42.671,58.207 48.878,52 63.427,52 68.7,57.273 68.7,62 61.4,62 61.4,68.497 67.578,74.675 79.2,74.675 79.2,70.6 86.3,70.6 91,65.9 91,59.6 85.5,59.6 85.5,61.5 87,61.5 87,65 71.745,65 71.745,54.968 61.845,45.069 46.105,45.069 37.755,53.419 7.581,53.419 4.1,56.9 4.1,70
+5V on SIG "+5V_L03_P004" (solid, remove dead copper, pour order 4): 63.232,20.127 67.6,20.127 67.6,16.535 73.664,16.535 79,21.87 79,24.1 76.901,26.199 76.901,31.285 81.2,31.285 81.2,21.4 73.8,14 63.232,14
GND on GND "GND_L02_P001" (solid, remove dead copper, pour order 1): 0,6.5 0,15.521 cw(c1.811,15.521) 0.53,16.802 0.531,16.802 0.971,17.241 ccw(c-0.31,18.521) 1.501,18.521 1.501,34.727 ccw(c-0.31,34.727) 0.971,36.008 0.531,36.447 0.53,36.447 cw(c1.811,37.727) 0,37.727 0,73.5 cw(c6.5,73.5) 6.5,80 21.501,80 cw(c21.501,79.397) 21.928,79.824 22.074,79.677 ccw(c22.501,80.104) 22.501,79.5 30.501,79.5 ccw(c30.501,80.104) 30.928,79.677 31.074,79.824 cw(c31.501,79.397) 31.501,80 99.499,80 cw(c99.499,80) 99.5,80 cw(c99.5,73.5) 106,73.5 106,6.5 cw(c99.5,6.5) 99.5,0 6.5,0 cw(c6.5,6.5)
GND on BOTTOM "GND_L04_P003" (solid, remove dead copper, pour order 3): 0,6.5 0,15.521 cw(c1.811,15.521) 0.53,16.802 0.531,16.802 0.971,17.241 ccw(c-0.31,18.521) 1.501,18.521 1.501,34.727 ccw(c-0.31,34.727) 0.971,36.008 0.531,36.447 0.53,36.447 cw(c1.811,37.727) 0,37.727 0,73.5 cw(c6.5,73.5) 6.5,80 21.501,80 cw(c21.501,79.397) 21.928,79.824 22.074,79.677 ccw(c22.501,80.104) 22.501,79.5 30.501,79.5 ccw(c30.501,80.104) 30.928,79.677 31.074,79.824 cw(c31.501,79.397) 31.501,80 99.499,80 cw(c99.499,80) 99.5,80 cw(c99.5,73.5) 106,73.5 106,6.5 cw(c99.5,6.5) 99.5,0 6.5,0 cw(c6.5,6.5)
GND on TOP "GND_L01_P006" (solid, remove dead copper, pour order 6): 0,6.5 0,15.521 cw(c1.811,15.521) 0.53,16.802 0.531,16.802 0.971,17.241 ccw(c-0.31,18.521) 1.501,18.521 1.501,34.727 ccw(c-0.31,34.727) 0.971,36.008 0.531,36.447 0.53,36.447 cw(c1.811,37.727) 0,37.727 0,73.5 cw(c6.5,73.5) 6.5,80 21.501,80 cw(c21.501,79.397) 21.928,79.824 22.074,79.677 ccw(c22.501,80.104) 22.501,79.5 30.501,79.5 ccw(c30.501,80.104) 30.928,79.677 31.074,79.824 cw(c31.501,79.397) 31.501,80 99.499,80 cw(c99.499,80) 99.5,80 cw(c99.5,73.5) 106,73.5 106,6.5 cw(c99.5,6.5) 99.5,0 6.5,0 cw(c6.5,6.5)

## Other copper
TOP:
  pour cut-out: 52.4,22.508 52.4,19.808 55,19.808 55,22.508
  pour cut-out: 45.93,34.054 45.93,31.354 48.53,31.354 48.53,34.054
  pour cut-out: 45.93,45.346 45.93,48.046 48.53,48.046 48.53,45.346
  pour cut-out: 52.4,27.8 52.4,30.5 55,30.5 55,27.8

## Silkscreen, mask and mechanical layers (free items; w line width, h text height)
Route Tool Path:
  lines w2: -1,7.5 -1,6.5 ; -1,13.5 -1,15.522 ; -1,61.503 -1,51.114 -1,37.727 ; -1,67.503 -1,73.503 cw(c6.5,73.5) 6.498,81 ; 6.5,81 21.501,81 ; 99.502,81 cw(c99.5,73.5) 107,73.503 107,67.503 ; 107,9.498 107,6.5 ; 107,15.498 107,61.503 ; -1,6.5 ccw(c6.5,6.5) 6.5,-1 ; -1,6.5 ccw(c0,6.5) -1,6.5 ; -1,6.5 ccw(c0,6.5) -1,6.5 ; -1,15.522 ccw(c1.811,15.521) -1,15.521 ; -1,15.522 cw(c1.811,15.521) -0.177,17.509 ; -1,15.521 -1,15.522 ; -1,37.727 ccw(c1.811,37.727) -0.177,35.74 ccw(c0.53,36.447) -0.15,35.714 ; -1,37.727 -1,37.727 ; -0.177,17.509 cw(c0.53,16.802) -0.15,17.535 ; -0.177,17.509 cw(c0.53,16.802) -0.15,17.535 ; -0.15,17.535 0.262,17.947 ; -0.15,35.714 0.262,35.302 ; -0.15,35.714 -0.15,35.714 ; 0.262,17.947 cw(c0.971,17.241) 0.264,17.948 ; 0.262,17.947 0.264,17.948 ; 0.262,35.302 ccw(c0.971,36.008) 0.264,35.3 ; 0.262,35.302 0.264,35.3 ; 0.264,17.948 ccw(c-0.31,18.521) 0.501,18.521 ; 0.264,35.3 ccw(c-0.31,34.727) 0.264,35.3 ; 0.264,35.3 cw(c-0.31,34.727) 0.501,34.727 ; 0.501,18.521 cw(c1.501,18.521) 0.501,18.524 ; 0.501,18.521 0.501,18.524 ; 0.501,18.524 0.501,34.725 ; 0.501,34.725 cw(c1.501,34.727) 0.501,34.727 ; 0.501,34.725 0.501,34.727 ; 6.5,-1 99.5,-1 ; 6.5,-1 6.5,-1 ; 6.5,-1 6.5,-1 ; 21.501,81 cw(c21.501,79.397) 21.505,81 ; 21.501,81 cw(c21.501,80) 21.505,81 ; 21.501,81 ccw(c21.501,80) 21.501,81 ; 21.505,81 cw(c21.501,79.397) 22.632,80.533 ; 22.632,80.533 cw(c21.501,79.397) 22.635,80.531 ; 22.632,80.533 cw(c21.928,79.824) 22.635,80.531 ; 22.635,80.531 22.665,80.5 30.337,80.5 30.367,80.531 cw(c31.501,79.397) 31.497,81 ; 31.497,81 cw(c31.501,79.397) 31.501,81 ; 31.497,81 cw(c31.501,80) 31.501,81 ; 31.501,81 99.499,81 ; 99.5,-1 ccw(c99.5,6.5) 99.502,-1 ; 99.5,-1 ccw(c99.5,0) 99.502,-1 ; 99.499,81 cw(c99.499,80) 99.527,81 ccw(c99.499,80) 99.499,81 ; 99.502,-1 ccw(c99.5,6.5) 107,6.498 ; 107,6.498 ccw(c106,6.5) 107,6.5 ; 107,6.498 ccw(c99.5,6.5) 107,6.5 ; 6.473,81 cw(c6.5,80) 6.5,81 ccw(c6.5,80) 6.473,81 ; 32.001,33.227 32.001,46.227 36.501,46.227 36.501,33.227 32.001,33.227
Outline:
  lines w0.1: 0,73.726 cw(c0,73.724) 0.001,73.724 ; 0.53,16.802 ccw(c1.811,15.521) 0,15.521 0,6.5 ; 0.53,36.447 cw(c1.811,37.727) 0,37.727 0,73.5 ; 0.531,16.802 0.971,17.241 ccw(c-0.31,18.521) 1.501,18.521 ; 0.531,36.447 0.971,36.008 cw(c-0.31,34.727) 1.501,34.727 ; 1.501,34.727 ccw(c1.501,34.727) 1.501,34.727 ; 0,6.5 ccw(c6.5,6.5) 6.5,0 ; 0,6.5 ccw(c6.5,6.5) 6.5,0 ; 0,73.5 cw(c6.5,73.5) 6.5,80 ; 0,73.5 cw(c6.5,73.5) 6.5,80 ; 1.501,18.521 ccw(c1.501,18.521) 1.501,18.521 ; 1.501,18.521 1.501,34.727 ; 6.5,0 99.5,0 ; 6.5,80 21.501,80 ; 21.501,80 ccw(c21.501,80) 21.501,80 ; 21.501,80 cw(c21.501,79.397) 21.928,79.824 22.001,79.75 22.074,79.677 ccw(c22.501,80.104) 22.501,79.5 30.501,79.5 ccw(c30.501,80.104) 30.928,79.677 31.001,79.75 31.074,79.824 cw(c31.501,79.397) 31.501,80 99.499,80 cw(c99.499,80) 99.5,80 ; 99.5,0 ccw(c99.5,6.5) 106,6.5 ; 99.5,0 ccw(c99.5,6.5) 106,6.5 ; 99.5,80 cw(c99.5,73.5) 106,73.5 ; 99.5,80 cw(c99.5,73.5) 106,73.5 ; 106,6.5 106,73.5 ; 31.001,33.227 ccw(c32.001,33.227) 32.001,32.227 36.501,32.227 ccw(c36.501,33.227) 37.501,33.227 37.501,46.227 ccw(c36.501,46.227) 36.501,47.227 33.001,47.227 32.001,47.227 ccw(c32.001,46.227) 31.001,46.227 31.001,33.227
Outline Arducam Breakout:
  lines w0.127: 37.608,46.454 37.608,76.954 68.108,76.954 68.108,46.454 37.608,46.454
OutlineGIGA:
  drawing of 255 lines, arcs and shapes, not listed
OutlinePortenta:
  lines w0.05: 50.938,34.97 52.938,34.97 ; 52.938,32.97 52.938,34.97 ; 52.938,36.97 52.938,34.97 ; 54.938,34.97 52.938,34.97
OutlineDisplay:
  drawing of 697 lines, arcs and shapes, not listed
  text "1" at 45.959,44.379 h1 r90
  text "20" at 45.959,34.893 h1 r90
  text "1" at 51.427,27.146 h1.35 r270
  text "8" at 51.427,24.004 h1.35 r270
  text "A" at 9.038,22.02 h1.13 r270
  text "A" at 13.869,21.465 h0.38 r90
  text "K" at 9.093,21.156 h1.13 r270
  text "K" at 13.858,20.556 h0.38 r90
OutlineFlatCable:
  lines w0.05: 54.301,37.301 103.051,37.301 ; 87.951,32.051 54.301,32.051 54.301,42.551 87.951,42.551 ; 102.051,9.371 102.051,13.801 103.051,13.801 ; 102.051,67.631 102.051,60.801 103.051,60.801 ; 103.051,13.801 87.951,13.801 87.951,60.801 103.051,60.801 ; 103.051,13.801 103.051,60.801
